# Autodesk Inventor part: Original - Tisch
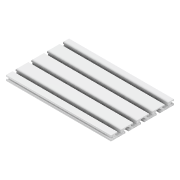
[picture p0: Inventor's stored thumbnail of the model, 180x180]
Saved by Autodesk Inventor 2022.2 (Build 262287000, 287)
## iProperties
Created: 2024-09
Part Number: Original - Tisch
Material: Alluminio 6061
Document SubType Name: Modeling
Designer: 18907419
Density: 2.7 g/cm^3
Appearance: Alluminio - Piatto
Author: 18907419
Revision Number: ANY
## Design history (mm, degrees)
feature "Schnitt-Linear austragen5"
node "Solido1"
